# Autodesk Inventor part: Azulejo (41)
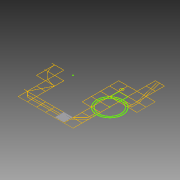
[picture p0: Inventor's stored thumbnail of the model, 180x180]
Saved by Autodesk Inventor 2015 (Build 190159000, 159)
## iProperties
Created: 2015-04
Part Number: Azulejo (41)
Material: Genérico
Document SubType Name: Modeling
Designer: Felipe
Density: 1 g/cm^3
Appearance: Padrão
Author: Felipe
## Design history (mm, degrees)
sketch "Sketch1"
  geometry: L1 (-1510, -7490)-(-1510, -6010); L2 (-3010, -1490)-(-3010, -10); L3 (-2990, 10)-(-1510, 10); L4 (-1510, -10)-(-2990, -10); L5 (-1510, -1490)-(-1510, -10); L6 (-1490, -10)-(-1490, -1490); L7 (-1490, -1490)-(-10, -1490); L8 (-10, -1510)-(-1490, -1510); L9 (-10, -2990)-(-10, -1510); L10 (-10, -5990)-(-10, -4510); L11 (-1490, -7490)-(-10, -7490); L12 (4490, -6010)-(3010, -6010); L13 (10, -1510)-(10, -2990); L14 (10, -3010)-(10, -4490); L15 (10, -4510)-(10, -5990); L16 (10, -5990)-(1490, -5990); L17 (1490, -6010)-(10, -6010); L18 (10, -7490)-(1490, -7490); L19 (1510, -5990)-(2990, -5990); L20 (2990, -6010)-(1510, -6010); L21 (1510, -7490)-(2990, -7490); L22 (4490, 1510)-(4490, 2990); L23 (4490, 10)-(4490, 1490); L24 (4490, -1490)-(4490, -10); L25 (4490, -2990)-(4490, -1510); L26 (3010, -5990)-(4490, -5990); L27 (3010, -7490)-(4490, -7490); L28 (4510, 3010)-(5990, 3010); L29 (5990, 2990)-(4510, 2990); L30 (4510, 2990)-(4510, 1510); L31 (4510, 1510)-(5990, 1510); L32 (5990, 1510)-(5990, 1740.185); L33 (5990, 1760.2)-(5990, 2259.8); L34 (5990, 2279.815)-(5990, 2990); L35 (5990, 1490)-(4510, 1490); L36 (4510, 1490)-(4510, 10); L37 (4510, 10)-(5990, 10); L38 (5990, 10)-(5990, 1490); L39 (5975.983, -10)-(4510, -10); L40 (4510, -10)-(4510, -1490); L41 (5990, -1510)-(5782.897, -1510); L42 (5782.897, -1510)-(5688.66, -1510); L43 (5668.66, -1510)-(5482.895, -1510); L44 (5482.895, -1510)-(5388.656, -1510); L45 (5368.656, -1510)-(4510, -1510); L46 (4510, -1510)-(4510, -2990); L47 (4510, -2990)-(5975.983, -2990); L48 (5990, -2975.728)-(5990, -2837.377); L49 (5990, -2837.377)-(5990, -2536.247); L50 (5990, -2500.476)-(5990, -2317.632); L51 (5990, -2317.632)-(5990, -1510); L52 (5990, -3010)-(4510, -3010); L53 (5990, -4490)-(5990, -3010); L54 (4510, -5990)-(5990, -5990); L55 (5990, -5990)-(5990, -4510); L56 (4510, -7490)-(5990, -7490); L57 (5990, -7490)-(5990, -6310); L58 (5990, -6290)-(5990, -6010); L59 (7490, 4510)-(7490, 5990); L60 (6010, 3010)-(7490, 3010); L61 (7490, 3010)-(7490, 4490); L62 (7490, 2990)-(6010, 2990); L63 (6010, 2990)-(6010, 2279.815); L64 (6010, 2259.8)-(6010, 1760.2)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; A1 r 250 centre (6000, 2010) between (5990, 2259.8) and (5990, 1760.2); A2 r 250 centre (6000, 2010) between (6010, 1760.2) and (6010, 2259.8); A3 r 270 centre (6000, 2010) between (5990, 2279.815) and (5990, 1740.185); A4 r 270 centre (6000, 2010) between (6010, 1740.185) and (6010, 2279.815); A5 r 3010.017 centre (0, 0) between (-1490, -2615.358) and (-346.554, -2990); A6 r 2990.017 centre (0, 0) between (-1490, -2592.316) and (-10, -2990); A7 r 3010.017 centre (0, 0) between (-2603.863, -1510) and (-1510, -2603.863); A8 r 2990.017 centre (0, 0) between (-2580.717, -1510) and (-1510, -2580.717); A9 r 3010.017 centre (0, 0) between (-2990, -346.554) and (-2615.358, -1490); A10 r 2990.017 centre (0, 0) between (-2990, -10) and (-2592.316, -1490); A11 r 2131.367 centre (7500, -1500) between (7490, 631.344) and (6010, 24.017); A12 r 2131.367 centre (7500, -1500) between (5975.983, -10) and (5368.656, -1490); A13 r 2131.367 centre (7500, -1500) between (5368.656, -1510) and (5975.983, -2990); A14 r 2131.367 centre (7500, -1500) between (6010, -3024.017) and (7190, -3608.703); A15 r 1831.367 centre (7500, -1500) between (7490.321, 331.342) and (6463.753, 10); A16 r 1831.367 centre (7500, -1500) between (7489.976, 331.34) and (6010, -435.196); A17 r 1831.367 centre (7500, -1500) between (5990, -463.753) and (5668.66, -1490); A18 r 1831.367 centre (7500, -1500) between (5668.66, -1510) and (5990, -2536.247); A19 r 1831.367 centre (7500, -1500) between (6010, -2564.804) and (6435.196, -2990); A20 r 1831.367 centre (7500, -1500) between (6463.753, -3010) and (7490, -3331.34); A21 r 2111.367 centre (7500, -1500) between (7490.389, 611.346) and (6024.272, 10); A22 r 2111.367 centre (7500, -1500) between (5990, -24.272) and (5388.656, -1490); A23 r 2111.367 centre (7500, -1500) between (5388.656, -1510) and (5990, -2975.728); A24 r 2111.367 centre (7500, -1500) between (6024.272, -3010) and (7210, -3591.357); A25 r 1811.367 centre (7499.986, -1499.91) between (7490.524, 311.432) and (6499.51, 10.09); A26 r 1811.367 centre (7500, -1500) between (6469.975, -10) and (6010, -469.975); A27 r 1811.367 centre (7500, -1500) between (5990, -499.524) and (5688.66, -1490); A28 r 1811.367 centre (7500, -1500) between (5688.66, -1510) and (5990, -2500.476); A29 r 1811.367 centre (7500, -1500) between (6010, -2530.025) and (6469.975, -2990); A30 r 1811.367 centre (7500, -1500) between (6499.524, -3010) and (7490, -3311.34); A31 r 449.871 centre (7499.449, -4060.672) between (7510, -4510.419) and (7521.546, -4510); A32 r 2111.367 centre (7500, -1500) between (7490.019, 611.344) and (7490.389, 611.346); A33 r 1831.367 centre (7500, -1500) between (7489.976, 331.34) and (7490.321, 331.342); A34 r 1811.367 centre (7499.986, -1499.91) between (7489.986, 311.429) and (7490.524, 311.432); A35 r 2131.367 centre (7500, -1500) between (7510, -3631.344) and (7190, -3608.703); A36 r 2131.367 centre (7500, -1500) between (7210, -3611.546) and (7490, -3631.344); 12 further points
  constraints: 718 end point, 82 point on circle, 36 centre point, 14 point on line, 3 concentric, 2 parallel, 2 perpendicular, 1 collinear, 1 horizontal, 1 vertical, 1 other
extrude "Extrusion1" new body sketch "Sketch1" distance "d0" = 60; taper "d1" = 0 deg
extrude "Extrusion2" new body sketch "Sketch1" distance "d2" = 60; taper "d3" = 0 deg
extrude "Extrusion3" new body sketch "Sketch1" distance "d4" = 60; taper "d5" = 0 deg
body "Solid1"
body "Solid2"
body "Solid3"
